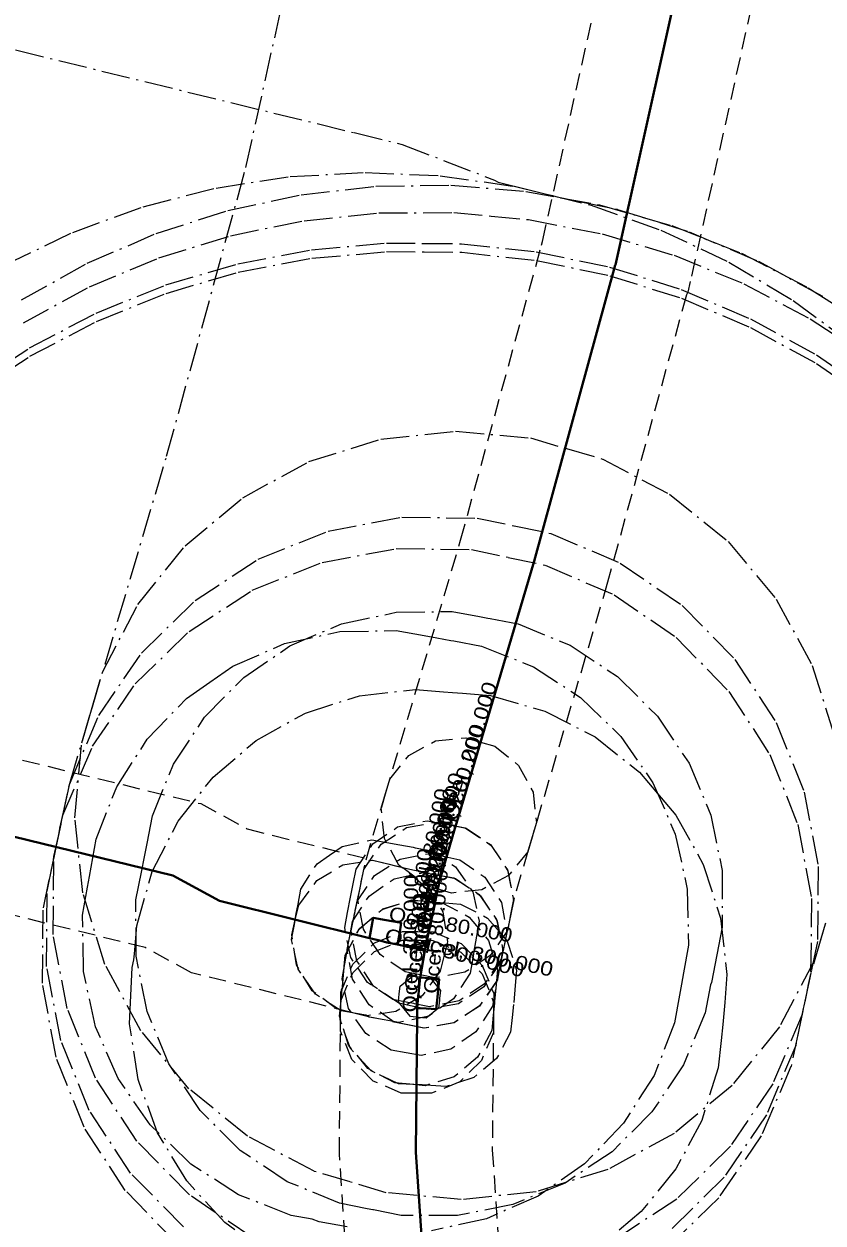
# Model space of a CAD drawing. Extents: x -640775 to -624586, y -1148563 to -1138811.
# Drawn here: x -626013.6 to -625971.8, y -1147211.8 to -1147149.1 of the extents above; entities that cross this region are included whole.
import ezdxf

# ---------------------------------------------------------------- set-up
doc = ezdxf.new("R2010")
doc.units = 0
doc.header["$LTSCALE"] = 0.3
for name, pattern in [('DOT_DASHED', [7.7, 5, -1.2, 0.3, -1.2]), ('DOTTED', [1.5, 0.3, -1.2]), ('MEDIUM_DASHED', [4.5, 3, -1.5])]:
    doc.linetypes.add(name, pattern=pattern)
for name, color, linetype, lineweight in [('1', 7, 'MEDIUM_DASHED', 13), ('34', 7, 'Continuous', 40), ('56', 7, 'DOTTED', 35), ('8', 7, 'MEDIUM_DASHED', 13)]:
    doc.layers.add(name, color=color, linetype=linetype, lineweight=lineweight)
doc.layers.add('40', color=7, linetype='Continuous')

msp = doc.modelspace()

# ---------------------------------------------------------------- linework, layer by layer
at = {"layer": '1', "linetype": 'DOT_DASHED'}
for points in [[(-626187.581, -1147108.078), (-625996.315, -1147154.761), (-625993.803, -1147155.374), (-625988.979, -1147157.237), (-625988.773, -1147157.349), (-625985.878, -1147158.067), (-625983.971, -1147158.54), (-625980.267, -1147159.856), (-625976.711, -1147161.528), (-625973.335, -1147163.541), (-625970.173, -1147165.875)], [(-625971.665, -1147196.155), (-625972.225, -1147198.044), (-625974.06, -1147201.53), (-625976.54, -1147204.591), (-625979.57, -1147207.109), (-625983.032, -1147208.988), (-625986.795, -1147210.156), (-625990.713, -1147210.566), (-625994.636, -1147210.205), (-625996.525, -1147209.645), (-625998.414, -1147209.085), (-626001.9, -1147207.25), (-626004.961, -1147204.77), (-626007.479, -1147201.74), (-626009.358, -1147198.278), (-626010.526, -1147194.515), (-626010.936, -1147190.597), (-626010.575, -1147186.674), (-626010.015, -1147184.785), (-626006.133, -1147171.69), (-626001.986, -1147156.587), (-625992.084, -1147112.063)], [(-626014.59, -1147161.679), (-626011.046, -1147159.978), (-626007.354, -1147158.633), (-626003.547, -1147157.656), (-625999.662, -1147157.058), (-625995.738, -1147156.842), (-625991.812, -1147157.013), (-625987.921, -1147157.567), (-625986.012, -1147158.034), (-625985.691, -1147158.112), (-625984.452, -1147158.371), (-625982.528, -1147158.772), (-625978.778, -1147159.947), (-625975.161, -1147161.483), (-625971.711, -1147163.367)], [(-626013.721, -1147163.498), (-626010.283, -1147161.592), (-626006.676, -1147160.033), (-626002.933, -1147158.835), (-625999.09, -1147158.009), (-625995.185, -1147157.565), (-625991.256, -1147157.505), (-625987.339, -1147157.83), (-625985.406, -1147158.184), (-625983.473, -1147158.538), (-625979.695, -1147159.621), (-625976.042, -1147161.07), (-625972.548, -1147162.869), (-625969.247, -1147165.003)], [(-626013.629, -1147164.702), (-626010.172, -1147162.832), (-626006.548, -1147161.31), (-626002.793, -1147160.151), (-625998.942, -1147159.365), (-625995.033, -1147158.96), (-625991.103, -1147158.941), (-625989.146, -1147159.124), (-625987.189, -1147159.307), (-625983.331, -1147160.054), (-625979.565, -1147161.177), (-625975.926, -1147162.663), (-625972.451, -1147164.498), (-625969.173, -1147166.665)], [(-626016.589, -1147168.172), (-626013.302, -1147166.018), (-626009.82, -1147164.196), (-626006.176, -1147162.724), (-626002.405, -1147161.617), (-625998.543, -1147160.885), (-625994.629, -1147160.534), (-625992.664, -1147160.552), (-625990.699, -1147160.569), (-625986.791, -1147160.99), (-625982.944, -1147161.791), (-625979.193, -1147162.965), (-625975.575, -1147164.501), (-625972.126, -1147166.384), (-625968.878, -1147168.597)], [(-626016.58, -1147168.611), (-626013.292, -1147166.458), (-626009.808, -1147164.638), (-626006.164, -1147163.168), (-626002.392, -1147162.062), (-625998.531, -1147161.331), (-625994.616, -1147160.983), (-625992.651, -1147161.001), (-625990.686, -1147161.019), (-625986.779, -1147161.441), (-625982.931, -1147162.244), (-625979.181, -1147163.42), (-625975.564, -1147164.957), (-625972.116, -1147166.842), (-625968.869, -1147169.056)], [(-626001.675, -1147212.539), (-626004.932, -1147210.323), (-626007.694, -1147207.514), (-626009.856, -1147204.221), (-626011.333, -1147200.568), (-626012.069, -1147196.698), (-626012.036, -1147192.759), (-626011.733, -1147191.301), (-626011.715, -1147191.136), (-626011.481, -1147190.076), (-626011.2, -1147188.799), (-626010.224, -1147185.495), (-626010.027, -1147184.827), (-626009.471, -1147182.937), (-626007.644, -1147179.447), (-626005.17, -1147176.38), (-626002.146, -1147173.855), (-625998.688, -1147171.969), (-625994.928, -1147170.793), (-625991.01, -1147170.374), (-625987.087, -1147170.727), (-625985.197, -1147171.283), (-625983.307, -1147171.839), (-625979.817, -1147173.666), (-625976.75, -1147176.14), (-625974.225, -1147179.164), (-625972.339, -1147182.622), (-625971.163, -1147186.382)], [(-626005.25, -1147211.992), (-626008.017, -1147209.188), (-626010.185, -1147205.898), (-626011.669, -1147202.249), (-626012.412, -1147198.38), (-626012.387, -1147194.44), (-626012.053, -1147192.818), (-626012.032, -1147192.625), (-626011.795, -1147191.558), (-626011.734, -1147191.281), (-626011.654, -1147190.917), (-626011.627, -1147190.789), (-626011.222, -1147188.861), (-626009.677, -1147185.237), (-626007.454, -1147181.985), (-626004.639, -1147179.228), (-626001.341, -1147177.074), (-625997.685, -1147175.604), (-625993.813, -1147174.876), (-625989.874, -1147174.917), (-625987.946, -1147175.322), (-625986.018, -1147175.727), (-625982.394, -1147177.272), (-625979.142, -1147179.495), (-625976.385, -1147182.31), (-625974.231, -1147185.608), (-625972.761, -1147189.264), (-625972.033, -1147193.136), (-625972.074, -1147197.075), (-625972.479, -1147199.003), (-625972.546, -1147199.323), (-625972.65, -1147199.793), (-625972.683, -1147199.955), (-625972.783, -1147200.436), (-625972.81, -1147200.569), (-625973.207, -1147202.498), (-625974.738, -1147206.128), (-625976.948, -1147209.39), (-625979.752, -1147212.157)], [(-626005.555, -1147212.903), (-626008.305, -1147210.082), (-626010.453, -1147206.778), (-626011.914, -1147203.12), (-626012.634, -1147199.246), (-626012.584, -1147195.307), (-626012.175, -1147193.38), (-626011.965, -1147192.39), (-626011.556, -1147190.463), (-626010.003, -1147186.843), (-626007.773, -1147183.595), (-626004.952, -1147180.845), (-626001.648, -1147178.697), (-625997.99, -1147177.236), (-625994.116, -1147176.516), (-625990.177, -1147176.566), (-625988.25, -1147176.975), (-625986.323, -1147177.384), (-625982.703, -1147178.937), (-625979.455, -1147181.167), (-625976.705, -1147183.988), (-625974.557, -1147187.292), (-625973.096, -1147190.95), (-625972.376, -1147194.824), (-625972.426, -1147198.763), (-625972.835, -1147200.69), (-625973.045, -1147201.68), (-625973.454, -1147203.607), (-625975.007, -1147207.227), (-625977.237, -1147210.475), (-625980.058, -1147213.225)], [(-625996.686, -1147211.997), (-625998.14, -1147211.737), (-625998.515, -1147211.591), (-625999.622, -1147211.391), (-626002.372, -1147210.31), (-626004.858, -1147208.713), (-626006.985, -1147206.662), (-626008.672, -1147204.236), (-626009.852, -1147201.527), (-626010.481, -1147198.64), (-626010.535, -1147195.686), (-626010.273, -1147194.232), (-626010.17, -1147193.663), (-626010.083, -1147193.177), (-626009.822, -1147191.722), (-626008.741, -1147188.97), (-626007.144, -1147186.482), (-626005.093, -1147184.354), (-626003.879, -1147183.51), (-626002.665, -1147182.667), (-625999.955, -1147181.486), (-625997.067, -1147180.857), (-625994.111, -1147180.804), (-625992.657, -1147181.066), (-625991.984, -1147181.187), (-625991.255, -1147181.318), (-625991.101, -1147181.347), (-625989.657, -1147181.616), (-625986.928, -1147182.704), (-625984.463, -1147184.3), (-625982.353, -1147186.345), (-625980.681, -1147188.76), (-625979.508, -1147191.453), (-625978.88, -1147194.323), (-625978.821, -1147197.26), (-625979.077, -1147198.706), (-625979.183, -1147199.305), (-625979.283, -1147199.866), (-625979.543, -1147201.32), (-625980.619, -1147204.072), (-625982.212, -1147206.561), (-625984.26, -1147208.691), (-625986.684, -1147210.381), (-625989.391, -1147211.565), (-625992.277, -1147212.198)], [(-626000.7, -1147213.52), (-626003.082, -1147211.772), (-626005.078, -1147209.593), (-626006.611, -1147207.067), (-626007.621, -1147204.29), (-626008.071, -1147201.37), (-626008.006, -1147199.894), (-626007.941, -1147198.418), (-626007.844, -1147198.022), (-626007.819, -1147197.717), (-626007.698, -1147196.245), (-626006.885, -1147193.404), (-626005.534, -1147190.776), (-626003.696, -1147188.463), (-626001.442, -1147186.552), (-625998.859, -1147185.118), (-625996.045, -1147184.216), (-625993.109, -1147183.88), (-625991.637, -1147184.001), (-625991.167, -1147184.039), (-625990.646, -1147184.082), (-625989.173, -1147184.203), (-625986.332, -1147185.015), (-625983.703, -1147186.365), (-625981.389, -1147188.203), (-625980.433, -1147189.33), (-625979.477, -1147190.457), (-625978.043, -1147193.04), (-625977.14, -1147195.854), (-625976.803, -1147198.789), (-625976.924, -1147200.262), (-625977.018, -1147201.416), (-625977.11, -1147202.248), (-625977.267, -1147203.678), (-625978.12, -1147206.427), (-625979.481, -1147208.964), (-625981.298, -1147211.195), (-625983.507, -1147213.041)], [(-625971.653, -1147196.113), (-625971.856, -1147196.805), (-625972.417, -1147198.704), (-625972.471, -1147198.962), (-625972.871, -1147200.891), (-625974.41, -1147204.518), (-625976.626, -1147207.775), (-625979.435, -1147210.537), (-625982.728, -1147212.699)]]:
    msp.add_lwpolyline(points, dxfattribs=at)
at = {"layer": '1'}
for points in [[(-625969.087, -1147119.211), (-625978.725, -1147162.548), (-625978.849, -1147163.105), (-625978.927, -1147163.247), (-625983.053, -1147178.278), (-625987.005, -1147191.607), (-625987.231, -1147192.37), (-625988.233, -1147193.606), (-625989.632, -1147194.365), (-625991.214, -1147194.531), (-625991.977, -1147194.305), (-625992.74, -1147194.079), (-625993.976, -1147193.077), (-625994.735, -1147191.678), (-625994.901, -1147190.096), (-625994.675, -1147189.333), (-625990.747, -1147176.082), (-625986.507, -1147160.641), (-625986.454, -1147160.45), (-625976.753, -1147116.829)], [(-625994.326, -1147248.902), (-625997.091, -1147208.197), (-625997.024, -1147200.962), (-625997.017, -1147200.166), (-625996.394, -1147198.702), (-625995.258, -1147197.587), (-625993.783, -1147196.992), (-625992.987, -1147196.999), (-625992.191, -1147197.006), (-625990.727, -1147197.629), (-625989.612, -1147198.765), (-625989.017, -1147200.24), (-625989.024, -1147201.036), (-625989.089, -1147207.963), (-625986.354, -1147248.218)]]:
    msp.add_lwpolyline(points, dxfattribs=at)
for points in [[(-626181.799, -1147154.781), (-626182.851, -1147146.289), (-626004.347, -1147189.857), (-626001.91, -1147191.181), (-625994.547, -1147193.008), (-625993.775, -1147193.2), (-625992.495, -1147194.144), (-625991.674, -1147195.507), (-625991.436, -1147197.081), (-625991.628, -1147197.853), (-625991.82, -1147198.625), (-625992.764, -1147199.905), (-625994.127, -1147200.726), (-625995.701, -1147200.964), (-625996.473, -1147200.772), (-626004.83, -1147198.699), (-626007.253, -1147197.383)], [(-625996.131, -1147194.862), (-625995.969, -1147194.083), (-625995.95, -1147193.992), (-625995.95, -1147193.945), (-625995.696, -1147192.792), (-625994.877, -1147190.019), (-625994.677, -1147189.341), (-625994.453, -1147188.578), (-625993.454, -1147187.339), (-625992.057, -1147186.578), (-625990.474, -1147186.408), (-625989.711, -1147186.633), (-625988.948, -1147186.857), (-625987.709, -1147187.856), (-625986.948, -1147189.253), (-625986.778, -1147190.836), (-625987.003, -1147191.599), (-625987.203, -1147192.281), (-625987.944, -1147194.788), (-625987.965, -1147194.885), (-625988.137, -1147195.709), (-625988.299, -1147196.488), (-625989.194, -1147197.804), (-625990.524, -1147198.677), (-625992.087, -1147198.974), (-625992.866, -1147198.812), (-625993.645, -1147198.65), (-625994.961, -1147197.755), (-625995.834, -1147196.425)], [(-625988.127, -1147195.659), (-625988.279, -1147196.44), (-625988.31, -1147196.486), (-625988.449, -1147197.183), (-625988.605, -1147197.963), (-625989.49, -1147199.286), (-625990.814, -1147200.168), (-625992.375, -1147200.477), (-625993.155, -1147200.321), (-625993.186, -1147200.315), (-625993.51, -1147200.251), (-625994.29, -1147200.097), (-625995.613, -1147199.216), (-625996.499, -1147197.896), (-625996.813, -1147196.337), (-625996.66, -1147195.557), (-625996.503, -1147194.756), (-625996.365, -1147194.053), (-625996.213, -1147193.279), (-625995.344, -1147191.963), (-625994.041, -1147191.075), (-625992.498, -1147190.749), (-625991.722, -1147190.89), (-625991.348, -1147190.958), (-625991.29, -1147190.97), (-625990.509, -1147191.122), (-625989.182, -1147192), (-625988.292, -1147193.319), (-625987.975, -1147194.878)], [(-625996.318, -1147195.734), (-625996.289, -1147195.592), (-625996.27, -1147195.501), (-625996.27, -1147195.452), (-625996.111, -1147194.734), (-625996.011, -1147194.279), (-625995.968, -1147194.075), (-625995.804, -1147193.296), (-625994.907, -1147191.982), (-625993.574, -1147191.112), (-625992.011, -1147190.818), (-625991.232, -1147190.981), (-625990.453, -1147191.145), (-625989.139, -1147192.042), (-625988.269, -1147193.375), (-625987.975, -1147194.938), (-625988.138, -1147195.717), (-625988.189, -1147195.961), (-625988.299, -1147196.46), (-625988.3, -1147196.465), (-625988.453, -1147197.206), (-625988.482, -1147197.346), (-625988.642, -1147198.125), (-625989.535, -1147199.443), (-625990.864, -1147200.318), (-625992.427, -1147200.618), (-625993.206, -1147200.458), (-625993.985, -1147200.298), (-625995.303, -1147199.405), (-625996.178, -1147198.076), (-625996.478, -1147196.513)], [(-625994.753, -1147201.168), (-625995.536, -1147201.028), (-625995.706, -1147200.919), (-625996.219, -1147200.827), (-625997.002, -1147200.686), (-625998.341, -1147199.826), (-625999.249, -1147198.519), (-625999.588, -1147196.964), (-625999.447, -1147196.181), (-625999.344, -1147195.61), (-625999.256, -1147195.121), (-625999.115, -1147194.337), (-625998.256, -1147192.997), (-625997.602, -1147192.543), (-625996.948, -1147192.089), (-625995.392, -1147191.75), (-625994.609, -1147191.892), (-625993.93, -1147192.014), (-625993.231, -1147192.139), (-625993.116, -1147192.161), (-625992.338, -1147192.306), (-625991.01, -1147193.166), (-625990.11, -1147194.466), (-625989.771, -1147196.011), (-625989.909, -1147196.79), (-625990.014, -1147197.381), (-625990.112, -1147197.933), (-625990.252, -1147198.716), (-625991.11, -1147200.057), (-625992.415, -1147200.967), (-625993.97, -1147201.308)], [(-625991.084, -1147201.312), (-625992.647, -1147201.608), (-625993.426, -1147201.446), (-625994.85, -1147201.149), (-625995.501, -1147201.019), (-625995.786, -1147200.944), (-625996.038, -1147200.879), (-625996.46, -1147200.776), (-625997.233, -1147200.587), (-625998.516, -1147199.646), (-625999.342, -1147198.286), (-625999.585, -1147196.713), (-625999.396, -1147195.94), (-625999.207, -1147195.167), (-625998.266, -1147193.884), (-625996.906, -1147193.058), (-625995.333, -1147192.815), (-625994.56, -1147193.004), (-625994.082, -1147193.121), (-625993.764, -1147193.204), (-625993.699, -1147193.221), (-625993.25, -1147193.311), (-625991.794, -1147193.614), (-625991.015, -1147193.776), (-625989.7, -1147194.672), (-625988.828, -1147196.004), (-625988.532, -1147197.567), (-625988.694, -1147198.346), (-625988.856, -1147199.125), (-625989.752, -1147200.44)], [(-625996.397, -1147199.043), (-625996.688, -1147197.478), (-625996.523, -1147196.7), (-625996.313, -1147195.71), (-625996.148, -1147194.932), (-625995.247, -1147193.62), (-625993.913, -1147192.753), (-625992.348, -1147192.462), (-625991.57, -1147192.627), (-625990.792, -1147192.792), (-625989.48, -1147193.693), (-625988.613, -1147195.027), (-625988.322, -1147196.592), (-625988.487, -1147197.37), (-625988.697, -1147198.36), (-625988.862, -1147199.138), (-625989.763, -1147200.45), (-625991.097, -1147201.317), (-625992.662, -1147201.608), (-625993.44, -1147201.443), (-625994.218, -1147201.278), (-625995.53, -1147200.377)], [(-625996.614, -1147200.568), (-625996.948, -1147199.013), (-625996.805, -1147198.23), (-625996.545, -1147196.81), (-625996.402, -1147196.027), (-625995.538, -1147194.691), (-625994.228, -1147193.786), (-625992.673, -1147193.452), (-625991.89, -1147193.595), (-625991.107, -1147193.738), (-625989.771, -1147194.602), (-625988.866, -1147195.912), (-625988.532, -1147197.467), (-625988.675, -1147198.25), (-625988.935, -1147199.67), (-625989.078, -1147200.453), (-625989.942, -1147201.789), (-625991.252, -1147202.694), (-625992.807, -1147203.028), (-625993.59, -1147202.885), (-625994.373, -1147202.742), (-625995.709, -1147201.878)], [(-625996.609, -1147202.487), (-625997.077, -1147200.966), (-625997.002, -1147200.174), (-625996.943, -1147199.543), (-625996.935, -1147199.458), (-625996.853, -1147198.578), (-625996.779, -1147197.786), (-625996.035, -1147196.378), (-625994.81, -1147195.363), (-625993.29, -1147194.893), (-625992.498, -1147194.967), (-625991.706, -1147195.041), (-625990.298, -1147195.785), (-625989.283, -1147197.01), (-625988.813, -1147198.53), (-625988.887, -1147199.322), (-625988.969, -1147200.196), (-625988.977, -1147200.285), (-625989.038, -1147200.926), (-625989.113, -1147201.718), (-625989.857, -1147203.124), (-625991.083, -1147204.139), (-625992.604, -1147204.607), (-625993.396, -1147204.532), (-625994.188, -1147204.457), (-625995.594, -1147203.713)], [(-625997.016, -1147200.375), (-625996.981, -1147199.58), (-625996.914, -1147199.436), (-625996.921, -1147199.414), (-625996.856, -1147198.621), (-625996.791, -1147197.828), (-625996.063, -1147196.413), (-625994.849, -1147195.384), (-625993.334, -1147194.899), (-625992.541, -1147194.964), (-625992.069, -1147195.002), (-625991.546, -1147195.045), (-625990.753, -1147195.11), (-625989.337, -1147195.838), (-625988.822, -1147196.445), (-625988.308, -1147197.052), (-625987.821, -1147198.567), (-625987.886, -1147199.36), (-625987.969, -1147200.363), (-625988.044, -1147201.045), (-625988.129, -1147201.815), (-625988.861, -1147203.18), (-625990.05, -1147204.173), (-625991.523, -1147204.651), (-625992.296, -1147204.597), (-625992.766, -1147204.565), (-625993.195, -1147204.546), (-625993.99, -1147204.511), (-625995.432, -1147203.839), (-625996.507, -1147202.665), (-625997.051, -1147201.17)], [(-625996.435, -1147203.234), (-625997.031, -1147201.759), (-625997.024, -1147200.963), (-625997.02, -1147200.514), (-625997.013, -1147199.719), (-625996.391, -1147198.254), (-625995.255, -1147197.139), (-625993.78, -1147196.543), (-625992.984, -1147196.55), (-625992.189, -1147196.557), (-625990.724, -1147197.179), (-625989.609, -1147198.315), (-625989.013, -1147199.79), (-625989.02, -1147200.586), (-625989.024, -1147201.035), (-625989.031, -1147201.83), (-625989.653, -1147203.295), (-625990.789, -1147204.41), (-625992.264, -1147205.006), (-625993.06, -1147204.999), (-625993.855, -1147204.992), (-625995.32, -1147204.37)]]:
    msp.add_lwpolyline(points, close=True, dxfattribs=at)
at = {"layer": '1', "linetype": 'DOT_DASHED'}
msp.add_lwpolyline([(-625977.329, -1147197.759), (-625977.611, -1147199.209), (-625977.659, -1147199.327), (-625977.662, -1147199.341), (-625977.952, -1147200.79), (-625979.085, -1147203.518), (-625980.73, -1147205.973), (-625982.821, -1147208.06), (-625985.28, -1147209.699), (-625988.011, -1147210.827), (-625990.909, -1147211.401), (-625993.864, -1147211.398), (-625995.313, -1147211.108), (-625995.348, -1147211.101), (-625995.642, -1147211.043), (-625997.09, -1147210.757), (-625999.819, -1147209.631), (-626002.277, -1147207.995), (-626004.368, -1147205.911), (-626006.013, -1147203.459), (-626007.149, -1147200.733), (-626007.731, -1147197.839), (-626007.738, -1147194.887), (-626007.454, -1147193.438), (-626007.297, -1147192.636), (-626007.158, -1147191.932), (-626006.876, -1147190.495), (-626005.765, -1147187.785), (-626004.152, -1147185.34), (-626002.097, -1147183.254), (-625999.676, -1147181.605), (-625996.983, -1147180.455), (-625994.118, -1147179.847), (-625991.19, -1147179.805), (-625989.749, -1147180.068), (-625989.312, -1147180.148), (-625989.19, -1147180.172), (-625987.74, -1147180.454), (-625985.005, -1147181.573), (-625982.541, -1147183.204), (-625980.443, -1147185.284), (-625978.791, -1147187.734), (-625977.649, -1147190.459), (-625977.06, -1147193.354), (-625977.047, -1147196.309)], close=True, dxfattribs=at)
at = {"layer": '34'}
for p, q in [((-625995.51, -1147196.89), (-625995.407, -1147196.318)), ((-625992.61, -1147197.53), (-625992.4, -1147196.54)), ((-625992.4, -1147196.54), (-625992.371, -1147196.399)), ((-625992.61, -1147197.53), (-625994.05, -1147197.23)), ((-625992.87, -1147198.95), (-625992.61, -1147197.53)), ((-625992.87, -1147198.95), (-625992.397, -1147198.989)), ((-625993.024, -1147200.999), (-625993.02, -1147200.55))]:
    msp.add_line(p, q, dxfattribs=at)
for points in [[(-625982.63, -1147161.68), (-625972.92, -1147118.02), (-625970.46, -1147111.93)], [(-625995.51, -1147196.89), (-626003.37, -1147194.94), (-626005.8, -1147193.62), (-626182.325, -1147150.535)], [(-625990.84, -1147190.47), (-625986.9, -1147177.18), (-625982.65, -1147161.7), (-625982.63, -1147161.68)], [(-625992.053, -1147194.896), (-625991.95, -1147194.4), (-625991.95, -1147194.38), (-625991.82, -1147193.79), (-625991.04, -1147191.15), (-625990.84, -1147190.47)], [(-625992.371, -1147196.399), (-625992.406, -1147196.392), (-625992.735, -1147196.327), (-625992.578, -1147195.527), (-625992.44, -1147194.825), (-625992.089, -1147194.889), (-625992.053, -1147194.896)], [(-625992.205, -1147195.597), (-625992.1, -1147195.12), (-625992.053, -1147194.896)], [(-625995.407, -1147196.318), (-625995.319, -1147195.828), (-625994.637, -1147195.951)], [(-625994.637, -1147195.951), (-625993.95, -1147196.074), (-625993.848, -1147196.093), (-625993.952, -1147196.681), (-625994.05, -1147197.23)], [(-625992.371, -1147196.399), (-625992.27, -1147195.91), (-625992.27, -1147195.89), (-625992.205, -1147195.597)], [(-625994.775, -1147197.074), (-625995.06, -1147197), (-625995.51, -1147196.89)], [(-625994.05, -1147197.23), (-625994.6, -1147197.12), (-625994.775, -1147197.074)], [(-625993.02, -1147200.55), (-625992.96, -1147199.914), (-625992.952, -1147199.827), (-625992.87, -1147198.95)], [(-625992.397, -1147198.989), (-625991.873, -1147199.032), (-625991.951, -1147199.98)], [(-625991.951, -1147199.98), (-625992.02, -1147200.607), (-625992.54, -1147200.571), (-625993.02, -1147200.55)], [(-625974.73, -1147394.1), (-625957.44, -1147358.3), (-625962.43, -1147347.19), (-625979.65, -1147331.1), (-625982.97, -1147319.57), (-625990.34, -1147248.56), (-625993.09, -1147208.08), (-625993.024, -1147200.999)]]:
    msp.add_lwpolyline(points, dxfattribs=at)
at = {"layer": '56'}
msp.add_lwpolyline([(-625992.96, -1147199.914), (-625992.84, -1147199.927), (-625992.852, -1147200.041)], dxfattribs=at)
at = {"layer": '8'}
msp.add_lwpolyline([(-625992.957, -1147201.036), (-625993.369, -1147200.993), (-625993.473, -1147200.864), (-625993.48, -1147200.863), (-625993.999, -1147200.218), (-625993.954, -1147199.806), (-625993.909, -1147199.394), (-625993.264, -1147198.875), (-625992.852, -1147198.92), (-625992.732, -1147198.933), (-625992.321, -1147198.977), (-625991.802, -1147199.621), (-625991.845, -1147200.032), (-625991.857, -1147200.146), (-625991.9, -1147200.558), (-625992.545, -1147201.079)], close=True, dxfattribs=at)

# ---------------------------------------------------------------- texts
at = {"layer": '40'}
for s, rotation, width, p in [('Ocel, 200.000', 73.61, 1.2, (-625990.94, -1147190.81)), ('Ocel, 200.000', 73.54, 1.2, (-625991.59, -1147193.012)), ('Ocel, 200.000', 77.492, 1.2, (-625992.216, -1147195.647)), ('Ocel, 80.000', 78.891, 1.15, (-625992.585, -1147195.565)), ('Ocel, 200.000', 78.378, 1.2, (-625992.386, -1147196.47)), ('Ocel, 200.000', 78.024, 1.2, (-625992.505, -1147197.035)), ('Ocel, 300.000', 79.624, 1.2, (-625992.74, -1147198.24)), ('Ocel, 300.000', 84.658, 1.2, (-625992.94, -1147199.7)), ('Ocel, 300.000', 89.49, 1.15, (-625993.022, -1147200.775)), ('Ocel, 80.000', 85.296, 1.15, (-625991.938, -1147199.821)), ('Ocel, 80.000', 349.849, 1.15, (-625994.546, -1147195.967)), ('Ocel, 300.000', 345.445, 1.2, (-625994.783, -1147197.072)), ('Ocel, 300.000', 348.232, 1.2, (-625993.33, -1147197.38))]:
    msp.add_text(s, height=0.75, rotation=rotation, dxfattribs=dict(at, width=width)).set_placement(p)

doc.saveas('drawing.dxf')
